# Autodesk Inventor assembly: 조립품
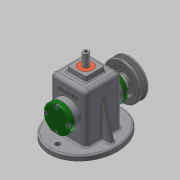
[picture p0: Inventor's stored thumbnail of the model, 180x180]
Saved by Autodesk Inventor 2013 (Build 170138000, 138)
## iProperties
Created: 2017-07
Part Number: 조립품
Document SubType Name: Assembly
Designer: Administrator
Author: Administrator
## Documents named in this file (16)
- C:\Users\Administrator\Desktop\470707V1031\조립품.iam
- C:\Users\Administrator\Desktop\470707V1031\본체.ipt
- C:\Users\Administrator\Desktop\470707V1031\DD\V벨트풀리.ipt
- C:\Users\Administrator\Desktop\470707V1031\DD\고정핀 1.2 x  8.ipt
- C:\Users\Administrator\Desktop\470707V1031\DD\뒤커버.ipt
- C:\Users\Administrator\Desktop\470707V1031\DD\링크.ipt
- C:\Users\Administrator\Desktop\470707V1031\DD\멈춤나사 M3x8.ipt
- C:\Users\Administrator\Desktop\470707V1031\DD\베어링 12 x 32 x 10.ipt
- C:\Users\Administrator\Desktop\470707V1031\DD\볼트 M4 x 12.ipt
- C:\Users\Administrator\Desktop\470707V1031\DD\부시.ipt
- C:\Users\Administrator\Desktop\470707V1031\DD\슬라이드.ipt
- C:\Users\Administrator\Desktop\470707V1031\DD\앞커버.ipt
- C:\Users\Administrator\Desktop\470707V1031\DD\오일실 12 25 7.ipt
- C:\Users\Administrator\Desktop\470707V1031\DD\키 4 x 4 x 10.ipt
- C:\Users\Administrator\Desktop\470707V1031\DD\편심축.ipt
- C:\Users\Administrator\Desktop\470707V1031\DD\핀 5 x 18.ipt
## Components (3 placed, 3 different names)
1. V벨트풀리:1
2. 고정핀 1.2 x  8:1
3. 핀 5 x 18:1
